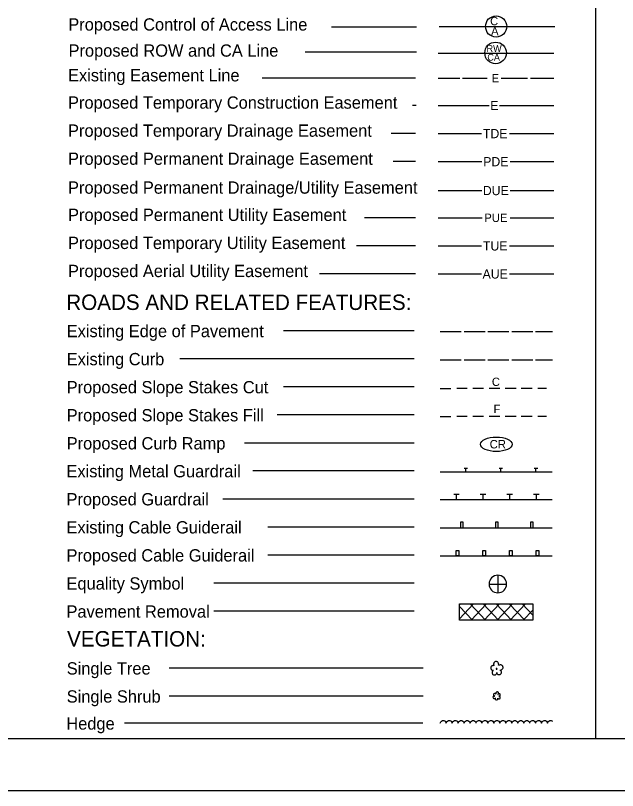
# Model space of a CAD drawing. Extents: x 2040834 to 2047174, y 618431 to 621625.
# Drawn here: x 2045579 to 2046085, y 620341 to 620991 of the extents above; entities that cross this region are included whole.
import ezdxf

# ---------------------------------------------------------------- set-up
doc = ezdxf.new("R2010")
doc.units = 0
doc.layers.add('Default', color=7, linetype='Continuous')

msp = doc.modelspace()

# ---------------------------------------------------------------- linework, layer by layer
at = {"layer": 'Default'}
for p, q in [((2046066.04, 621580.79), (2046066.01, 620384.96)), ((2045916.06, 620981.49), (2045844.59, 620981.49)), ((2045934.93, 620981.94), (2046032.04, 620981.94)), ((2045915.94, 620960.59), (2045822.52, 620960.59)), ((2045934.07, 620959.68), (2046031.18, 620959.68)), ((2045915.19, 620938.67), (2045786.59, 620938.67)), ((2045934.06, 620938.67), (2045952.32, 620938.67)), ((2045954.68, 620938.67), (2045975.27, 620938.67)), ((2045987.05, 620938.67), (2046009.12, 620938.67)), ((2046011.47, 620938.67), (2046031.17, 620938.67)), ((2045915.64, 620915.78), (2045912.68, 620915.78)), ((2045934.06, 620915.78), (2045937.14, 620915.78)), ((2045937.14, 620915.78), (2045976.86, 620915.78)), ((2045985.69, 620915.78), (2046025.42, 620915.78)), ((2046025.42, 620915.78), (2046031.17, 620915.78)), ((2045915.19, 620892.23), (2045894.6, 620892.23)), ((2045934.06, 620892.23), (2045938, 620892.23)), ((2045938, 620892.23), (2045970.37, 620892.23)), ((2045993.92, 620892.23), (2046026.29, 620892.23)), ((2046026.29, 620892.23), (2046031.17, 620892.23)), ((2045915.19, 620868.69), (2045896.35, 620868.69)), ((2045934.06, 620868.69), (2045938.53, 620868.69)), ((2045938.53, 620868.69), (2045970.9, 620868.69)), ((2045994.45, 620868.69), (2046026.82, 620868.69)), ((2046026.82, 620868.69), (2046031.17, 620868.69)), ((2045934.06, 620844.47), (2045970.9, 620844.47)), ((2045994.45, 620844.47), (2046031.17, 620844.47)), ((2045915.19, 620821.6), (2045872.33, 620821.6)), ((2045934.06, 620821.6), (2045938.58, 620821.6)), ((2045938.58, 620821.6), (2045970.95, 620821.6)), ((2045994.49, 620821.6), (2046026.86, 620821.6)), ((2046026.86, 620821.6), (2046031.17, 620821.6)), ((2045915.19, 620798.06), (2045865.59, 620798.06)), ((2045934.06, 620798.06), (2045938, 620798.06)), ((2045938, 620798.06), (2045970.37, 620798.06)), ((2045993.92, 620798.06), (2046026.29, 620798.06)), ((2046026.29, 620798.06), (2046031.17, 620798.06)), ((2045915.19, 620774.51), (2045834.61, 620774.51)), ((2045934.06, 620774.51), (2045938, 620774.51)), ((2045938, 620774.51), (2045970.37, 620774.51)), ((2045993.92, 620774.51), (2046026.29, 620774.51)), ((2046026.29, 620774.51), (2046031.17, 620774.51)), ((2045914.06, 620726.81), (2045804.31, 620726.81)), ((2045935.87, 620726.13), (2045953.53, 620726.13)), ((2045955.88, 620726.13), (2045973.54, 620726.13)), ((2045975.89, 620726.13), (2045993.55, 620726.13)), ((2045995.9, 620726.13), (2046013.56, 620726.13)), ((2046015.91, 620726.13), (2046030.04, 620726.13)), ((2045914.06, 620703.27), (2045717.31, 620703.27)), ((2045935.87, 620702.59), (2045953.53, 620702.59)), ((2045955.88, 620702.59), (2045973.54, 620702.59)), ((2045975.89, 620702.59), (2045993.55, 620702.59)), ((2045995.9, 620702.59), (2046013.56, 620702.59)), ((2046015.91, 620702.59), (2046030.04, 620702.59)), ((2045914.06, 620679.73), (2045804.37, 620679.73)), ((2045935.87, 620678.49), (2045944.82, 620678.49)), ((2045958.59, 620678.49), (2045949.7, 620678.49)), ((2045972.13, 620678.49), (2045963.18, 620678.49)), ((2045985.96, 620678.49), (2045976.78, 620678.49)), ((2045999.44, 620678.49), (2045990.31, 620678.49)), ((2046013.03, 620678.49), (2046003.79, 620678.49)), ((2046025.15, 620678.49), (2046017.62, 620678.49)), ((2045914.06, 620656.18), (2045799.01, 620656.18)), ((2045935.87, 620654.95), (2045944.82, 620654.95)), ((2045958.59, 620654.95), (2045949.7, 620654.95)), ((2045972.13, 620654.95), (2045963.18, 620654.95)), ((2045985.96, 620654.95), (2045976.78, 620654.95)), ((2045999.44, 620654.95), (2045990.31, 620654.95)), ((2046013.03, 620654.95), (2046003.79, 620654.95)), ((2046025.15, 620654.95), (2046017.62, 620654.95)), ((2045914.06, 620632.64), (2045771.72, 620632.64)), ((2045955.86, 620611.51), (2045958.8, 620611.51)), ((2045957.33, 620608.57), (2045957.33, 620611.51)), ((2045985.29, 620611.51), (2045988.23, 620611.51)), ((2045986.76, 620608.57), (2045986.76, 620611.51)), ((2046014.71, 620611.51), (2046017.66, 620611.51)), ((2046016.19, 620608.57), (2046016.19, 620611.51)), ((2045913.88, 620609.24), (2045778.7, 620609.24)), ((2045935.69, 620608.57), (2046029.86, 620608.57)), ((2045913.88, 620585.7), (2045753.51, 620585.7)), ((2046029.86, 620585.02), (2045935.69, 620585.02)), ((2045947.14, 620589.67), (2045951.84, 620589.67)), ((2045949.49, 620585.02), (2045949.49, 620589.67)), ((2045969.5, 620589.67), (2045974.21, 620589.67)), ((2045971.85, 620585.02), (2045971.85, 620589.67)), ((2045991.86, 620589.67), (2045996.57, 620589.67)), ((2045994.22, 620585.02), (2045994.22, 620589.67)), ((2046014.23, 620589.67), (2046018.94, 620589.67)), ((2046016.58, 620585.02), (2046016.58, 620589.67)), ((2045913.88, 620562.16), (2045791.11, 620562.16)), ((2045935.69, 620561.48), (2046029.86, 620561.48)), ((2045913.88, 620538.62), (2045791.11, 620538.62)), ((2045935.69, 620537.94), (2046029.86, 620537.94)), ((2045984.21, 620521.74), (2045984.21, 620514.38)), ((2045913.88, 620515.07), (2045745.99, 620515.07)), ((2045976.86, 620514.38), (2045984.21, 620514.38)), ((2045984.21, 620514.38), (2045984.21, 620507.03)), ((2045984.21, 620514.38), (2045991.57, 620514.38)), ((2045952.11, 620497.76), (2046013.43, 620497.76)), ((2045952.11, 620483.98), (2045952.11, 620497.76)), ((2045952.11, 620497.05), (2045952.76, 620497.76)), ((2045952.11, 620485.34), (2045963.7, 620497.76)), ((2045963, 620483.98), (2045952.11, 620495.64)), ((2045973.94, 620483.98), (2045961, 620497.76)), ((2045961.7, 620483.98), (2045974.65, 620497.76)), ((2045984.83, 620483.98), (2045971.94, 620497.76)), ((2045972.59, 620483.98), (2045985.6, 620497.76)), ((2045995.78, 620483.98), (2045982.83, 620497.76)), ((2045983.54, 620483.98), (2045996.48, 620497.76)), ((2046006.73, 620483.98), (2045993.72, 620497.76)), ((2045994.48, 620483.98), (2046007.37, 620497.76)), ((2046013.43, 620488.4), (2046004.67, 620497.76)), ((2046013.43, 620497.76), (2046013.43, 620483.98)), ((2045913.88, 620491.53), (2045745.99, 620491.53)), ((2046005.37, 620483.98), (2046013.43, 620492.58)), ((2046013.43, 620483.98), (2045952.11, 620483.98)), ((2045921.62, 620443.81), (2045708.42, 620443.81)), ((2045921.62, 620420.27), (2045708.42, 620420.27)), ((2045921.31, 620397.6), (2045670.95, 620397.6)), ((2045935.89, 620397.6), (2045936.25, 620398.72)), ((2045936.25, 620398.72), (2045936.95, 620399.48)), ((2045936.95, 620399.48), (2045937.89, 620400.01)), ((2045937.89, 620400.01), (2045939.01, 620400.01)), ((2045939.01, 620400.01), (2045939.95, 620399.42)), ((2045939.95, 620399.42), (2045940.6, 620398.66)), ((2045940.6, 620398.66), (2045940.84, 620397.66)), ((2045940.9, 620397.6), (2045941.25, 620398.72)), ((2045941.25, 620398.72), (2045941.96, 620399.48)), ((2045941.96, 620399.48), (2045942.9, 620400.01)), ((2045942.9, 620400.01), (2045944.02, 620400.01)), ((2045944.02, 620400.01), (2045944.96, 620399.42)), ((2045944.96, 620399.42), (2045945.6, 620398.66)), ((2045945.6, 620398.66), (2045945.84, 620397.66)), ((2045945.9, 620397.6), (2045946.25, 620398.72)), ((2045946.25, 620398.72), (2045946.96, 620399.48)), ((2045946.96, 620399.48), (2045947.9, 620400.01)), ((2045947.9, 620400.01), (2045949.02, 620400.01)), ((2045949.02, 620400.01), (2045949.96, 620399.42)), ((2045949.96, 620399.42), (2045950.61, 620398.66)), ((2045950.61, 620398.66), (2045950.84, 620397.66)), ((2045950.9, 620397.6), (2045951.25, 620398.72)), ((2045951.25, 620398.72), (2045951.96, 620399.48)), ((2045951.96, 620399.48), (2045952.9, 620400.01)), ((2045952.9, 620400.01), (2045954.02, 620400.01)), ((2045954.02, 620400.01), (2045954.96, 620399.42)), ((2045954.96, 620399.42), (2045955.61, 620398.66)), ((2045955.61, 620398.66), (2045955.85, 620397.66)), ((2045955.9, 620397.6), (2045956.26, 620398.72)), ((2045956.26, 620398.72), (2045956.96, 620399.48)), ((2045956.96, 620399.48), (2045957.91, 620400.01)), ((2045957.91, 620400.01), (2045959.02, 620400.01)), ((2045959.02, 620400.01), (2045959.97, 620399.42)), ((2045959.97, 620399.42), (2045960.61, 620398.66)), ((2045960.61, 620398.66), (2045960.85, 620397.66)), ((2045960.91, 620397.6), (2045961.26, 620398.72)), ((2045961.26, 620398.72), (2045961.97, 620399.48)), ((2045961.97, 620399.48), (2045962.91, 620400.01)), ((2045962.91, 620400.01), (2045964.03, 620400.01)), ((2045964.03, 620400.01), (2045964.97, 620399.42)), ((2045964.97, 620399.42), (2045965.62, 620398.66)), ((2045965.62, 620398.66), (2045965.85, 620397.66)), ((2045965.91, 620397.6), (2045966.26, 620398.72)), ((2045966.26, 620398.72), (2045966.97, 620399.48)), ((2045966.97, 620399.48), (2045967.91, 620400.01)), ((2045967.91, 620400.01), (2045969.03, 620400.01)), ((2045969.03, 620400.01), (2045969.97, 620399.42)), ((2045969.97, 620399.42), (2045970.62, 620398.66)), ((2045970.62, 620398.66), (2045970.85, 620397.66)), ((2045970.91, 620397.6), (2045971.27, 620398.72)), ((2045971.27, 620398.72), (2045971.97, 620399.48)), ((2045971.97, 620399.48), (2045972.91, 620400.01)), ((2045972.91, 620400.01), (2045974.03, 620400.01)), ((2045974.03, 620400.01), (2045974.97, 620399.42)), ((2045974.97, 620399.42), (2045975.62, 620398.66)), ((2045975.62, 620398.66), (2045975.86, 620397.66)), ((2045975.91, 620397.6), (2045976.27, 620398.72)), ((2045976.27, 620398.72), (2045976.97, 620399.48)), ((2045976.97, 620399.48), (2045977.92, 620400.01)), ((2045977.92, 620400.01), (2045979.03, 620400.01)), ((2045979.03, 620400.01), (2045979.98, 620399.42)), ((2045979.98, 620399.42), (2045980.62, 620398.66)), ((2045980.62, 620398.66), (2045980.86, 620397.66)), ((2045980.92, 620397.6), (2045981.27, 620398.72)), ((2045981.27, 620398.72), (2045981.98, 620399.48)), ((2045981.98, 620399.48), (2045982.92, 620400.01)), ((2045982.92, 620400.01), (2045984.04, 620400.01)), ((2045984.04, 620400.01), (2045984.98, 620399.42)), ((2045984.98, 620399.42), (2045985.63, 620398.66)), ((2045985.63, 620398.66), (2045985.86, 620397.66)), ((2045985.92, 620397.6), (2045986.27, 620398.72)), ((2045986.27, 620398.72), (2045986.98, 620399.48)), ((2045986.98, 620399.48), (2045987.92, 620400.01)), ((2045987.92, 620400.01), (2045989.04, 620400.01)), ((2045989.04, 620400.01), (2045989.98, 620399.42)), ((2045989.98, 620399.42), (2045990.63, 620398.66)), ((2045990.63, 620398.66), (2045990.86, 620397.66)), ((2045990.92, 620397.6), (2045991.28, 620398.72)), ((2045991.28, 620398.72), (2045991.98, 620399.48)), ((2045991.98, 620399.48), (2045992.92, 620400.01)), ((2045992.92, 620400.01), (2045994.04, 620400.01)), ((2045994.04, 620400.01), (2045994.98, 620399.42)), ((2045994.98, 620399.42), (2045995.63, 620398.66)), ((2045995.63, 620398.66), (2045995.87, 620397.66)), ((2045995.93, 620397.6), (2045996.28, 620398.72)), ((2045996.28, 620398.72), (2045996.98, 620399.48)), ((2045996.98, 620399.48), (2045997.93, 620400.01)), ((2045997.93, 620400.01), (2045999.04, 620400.01)), ((2045999.04, 620400.01), (2045999.99, 620399.42)), ((2045999.99, 620399.42), (2046000.63, 620398.66)), ((2046000.63, 620398.66), (2046000.87, 620397.66)), ((2046000.93, 620397.6), (2046001.28, 620398.72)), ((2046001.28, 620398.72), (2046001.99, 620399.48)), ((2046001.99, 620399.48), (2046002.93, 620400.01)), ((2046002.93, 620400.01), (2046004.05, 620400.01)), ((2046004.05, 620400.01), (2046004.99, 620399.42)), ((2046004.99, 620399.42), (2046005.64, 620398.66)), ((2046005.64, 620398.66), (2046005.87, 620397.66)), ((2046005.93, 620397.6), (2046006.28, 620398.72)), ((2046006.28, 620398.72), (2046006.99, 620399.48)), ((2046006.99, 620399.48), (2046007.93, 620400.01)), ((2046007.93, 620400.01), (2046009.05, 620400.01)), ((2046009.05, 620400.01), (2046009.99, 620399.42)), ((2046009.99, 620399.42), (2046010.64, 620398.66)), ((2046010.64, 620398.66), (2046010.87, 620397.66)), ((2046010.93, 620397.6), (2046011.29, 620398.72)), ((2046011.29, 620398.72), (2046011.99, 620399.48)), ((2046011.99, 620399.48), (2046012.93, 620400.01)), ((2046012.93, 620400.01), (2046014.05, 620400.01)), ((2046014.05, 620400.01), (2046014.99, 620399.42)), ((2046014.99, 620399.42), (2046015.64, 620398.66)), ((2046015.64, 620398.66), (2046015.88, 620397.66)), ((2046015.94, 620397.6), (2046016.29, 620398.72)), ((2046016.29, 620398.72), (2046017, 620399.48)), ((2046017, 620399.48), (2046017.94, 620400.01)), ((2046017.94, 620400.01), (2046019.06, 620400.01)), ((2046019.06, 620400.01), (2046020, 620399.42)), ((2046020, 620399.42), (2046020.64, 620398.66)), ((2046020.64, 620398.66), (2046020.88, 620397.66)), ((2046020.94, 620397.6), (2046021.29, 620398.72)), ((2046021.29, 620398.72), (2046022, 620399.48)), ((2046022, 620399.48), (2046022.94, 620400.01)), ((2046022.94, 620400.01), (2046024.06, 620400.01)), ((2046024.06, 620400.01), (2046025, 620399.42)), ((2046025, 620399.42), (2046025.65, 620398.66)), ((2046025.65, 620398.66), (2046025.88, 620397.66)), ((2046025.94, 620397.6), (2046026.29, 620398.72)), ((2046026.29, 620398.72), (2046027, 620399.48)), ((2046027, 620399.48), (2046027.94, 620400.01)), ((2046027.94, 620400.01), (2046029.06, 620400.01)), ((2046029.06, 620400.01), (2046030, 620399.42)), ((2046030, 620399.42), (2046030.06, 620399.36)), ((2045118.13, 620384.96), (2047013.93, 620384.96)), ((2045074.38, 620341.21), (2047057.71, 620341.21))]:
    msp.add_line(p, q, dxfattribs=at)
for points in [[(2045952.73, 620561.48), (2045955.08, 620561.48), (2045955.08, 620566.19), (2045952.73, 620566.19)], [(2045982.15, 620561.48), (2045984.51, 620561.48), (2045984.51, 620566.19), (2045982.15, 620566.19)], [(2046011.58, 620561.48), (2046013.94, 620561.48), (2046013.94, 620566.19), (2046011.58, 620566.19)], [(2045949.18, 620542.65), (2045951.53, 620542.65), (2045951.53, 620537.94), (2045949.18, 620537.94)], [(2045971.55, 620542.65), (2045973.9, 620542.65), (2045973.9, 620537.94), (2045971.55, 620537.94)], [(2045993.91, 620542.65), (2045996.26, 620542.65), (2045996.26, 620537.94), (2045993.91, 620537.94)], [(2046016.27, 620542.65), (2046018.63, 620542.65), (2046018.63, 620537.94), (2046016.27, 620537.94)]]:
    msp.add_lwpolyline(points, close=True, dxfattribs=at)
for points in [[(2045984.64, 620446.27), (2045984.82, 620446.68), (2045984.91, 620447.1), (2045984.87, 620447.56), (2045984.78, 620447.98), (2045984.54, 620448.4), (2045984.31, 620448.72), (2045983.94, 620449.05), (2045983.57, 620449.23), (2045983.11, 620449.37), (2045982.69, 620449.37), (2045982.23, 620449.32), (2045981.81, 620449.18), (2045981.44, 620448.95), (2045981.11, 620448.63), (2045980.88, 620448.26), (2045980.7, 620447.84), (2045980.65, 620447.42), (2045980.65, 620446.96), (2045980.74, 620446.54), (2045980.93, 620446.13), (2045981.21, 620445.76), (2045980.84, 620445.94), (2045980.42, 620446.03), (2045980, 620445.99), (2045979.59, 620445.89), (2045979.21, 620445.71), (2045978.84, 620445.43), (2045978.61, 620445.11), (2045978.38, 620444.74), (2045978.29, 620444.36), (2045978.24, 620443.9), (2045978.29, 620443.48), (2045978.47, 620443.11), (2045978.7, 620442.74), (2045978.98, 620442.46), (2045979.35, 620442.23), (2045979.72, 620442.05), (2045980.14, 620442), (2045980.56, 620442), (2045980.19, 620441.82), (2045979.86, 620441.54), (2045979.63, 620441.21), (2045979.45, 620440.8), (2045979.35, 620440.38), (2045979.31, 620439.96), (2045979.4, 620439.55), (2045979.59, 620439.17), (2045979.82, 620438.8), (2045980.09, 620438.53), (2045980.46, 620438.29), (2045980.88, 620438.15), (2045981.3, 620438.11), (2045981.72, 620438.15), (2045982.13, 620438.25), (2045982.51, 620438.48), (2045982.83, 620438.76), (2045983.06, 620439.08), (2045983.25, 620439.45), (2045983.34, 620439.87)], [(2045983.34, 620443.67), (2045983.15, 620443.67), (2045982.97, 620443.62), (2045982.88, 620443.48), (2045982.83, 620443.3), (2045982.88, 620443.11), (2045983.02, 620442.97), (2045983.2, 620442.97), (2045983.39, 620443.02), (2045983.52, 620443.16), (2045983.57, 620443.34), (2045983.48, 620443.53), (2045983.34, 620443.67)], [(2045983.2, 620440.38), (2045983.25, 620439.92), (2045983.39, 620439.5), (2045983.62, 620439.13), (2045983.94, 620438.8), (2045984.31, 620438.57), (2045984.73, 620438.43), (2045985.19, 620438.39), (2045985.61, 620438.43), (2045986.03, 620438.57), (2045986.4, 620438.8), (2045986.72, 620439.08), (2045987, 620439.45), (2045987.14, 620439.87), (2045987.23, 620440.29), (2045987.19, 620440.75), (2045987.09, 620441.17), (2045986.86, 620441.58), (2045986.58, 620441.91), (2045986.21, 620442.14), (2045985.8, 620442.33), (2045986.26, 620442.28), (2045986.72, 620442.28), (2045987.14, 620442.42), (2045987.56, 620442.6), (2045987.93, 620442.88), (2045988.21, 620443.25), (2045988.44, 620443.67), (2045988.53, 620444.09), (2045988.58, 620444.55), (2045988.48, 620445.01), (2045988.34, 620445.43), (2045988.07, 620445.8), (2045987.74, 620446.13), (2045987.37, 620446.36), (2045986.91, 620446.54), (2045986.49, 620446.59), (2045986.03, 620446.59), (2045985.56, 620446.45), (2045985.19, 620446.22), (2045984.82, 620445.94)], [(2045982.64, 620421.98), (2045982.51, 620422.26), (2045982.23, 620422.49), (2045981.95, 620422.68), (2045981.62, 620422.72), (2045981.3, 620422.68), (2045980.98, 620422.58), (2045980.7, 620422.35), (2045980.51, 620422.07), (2045980.42, 620421.75), (2045980.42, 620421.42), (2045980.51, 620421.1), (2045980.7, 620420.82), (2045980.98, 620420.59), (2045981.3, 620420.45), (2045981.62, 620420.45), (2045981.3, 620420.5), (2045980.98, 620420.5), (2045980.7, 620420.41), (2045980.42, 620420.22), (2045980.24, 620419.99), (2045980.14, 620419.71), (2045980.09, 620419.39), (2045980.14, 620419.06), (2045980.28, 620418.78), (2045980.51, 620418.55), (2045980.79, 620418.41), (2045981.07, 620418.32), (2045981.39, 620418.37), (2045981.67, 620418.46), (2045981.95, 620418.64), (2045982.13, 620418.88), (2045982, 620418.55), (2045981.95, 620418.23), (2045982.04, 620417.9), (2045982.18, 620417.63), (2045982.41, 620417.35), (2045982.69, 620417.21), (2045983.02, 620417.12), (2045983.34, 620417.16), (2045983.66, 620417.26), (2045983.94, 620417.44), (2045984.13, 620417.72), (2045984.27, 620418.04), (2045984.27, 620418.37), (2045984.22, 620418.69), (2045984.36, 620418.46), (2045984.64, 620418.23), (2045984.91, 620418.13), (2045985.24, 620418.09), (2045985.56, 620418.13), (2045985.84, 620418.27), (2045986.07, 620418.51), (2045986.21, 620418.78), (2045986.26, 620419.11), (2045986.26, 620419.43), (2045986.12, 620419.71), (2045985.93, 620419.94), (2045985.7, 620420.13), (2045985.38, 620420.27), (2045985.05, 620420.27), (2045985.38, 620420.27), (2045985.7, 620420.36), (2045985.93, 620420.54), (2045986.17, 620420.82), (2045986.26, 620421.1), (2045986.26, 620421.42), (2045986.21, 620421.75), (2045986.03, 620422.03), (2045985.8, 620422.21), (2045985.47, 620422.35), (2045985.15, 620422.4), (2045984.87, 620422.31), (2045984.54, 620422.17), (2045984.36, 620421.93), (2045984.22, 620421.66)], [(2045984.08, 620421.66), (2045984.36, 620421.8), (2045984.59, 620422.07), (2045984.73, 620422.35), (2045984.78, 620422.68), (2045984.78, 620423), (2045984.64, 620423.32), (2045984.45, 620423.56), (2045984.22, 620423.79), (2045983.89, 620423.88), (2045983.57, 620423.93), (2045983.25, 620423.88), (2045982.97, 620423.74), (2045982.69, 620423.51), (2045982.55, 620423.23), (2045982.46, 620422.91), (2045982.46, 620422.58), (2045982.51, 620422.26), (2045982.69, 620421.98)]]:
    msp.add_lwpolyline(points, dxfattribs=at)
for centre, radius in [((2045982.77, 620982.06), 8.92), ((2045982.32, 620959.86), 9.08)]:
    msp.add_circle(centre, radius, dxfattribs=at)
for start, end in [(89.99439, 179.99893), (359.99439, 89.99893), (179.99439, 269.99892), (269.99439, 359.99893)]:
    msp.add_arc((2045984.21, 620514.38), 7.36, start, end, dxfattribs=at)
msp.add_ellipse((2045982.91, 620631.62), major_axis=(13.2, 0), ratio=0.462467, dxfattribs=at)

# ---------------------------------------------------------------- texts
for s, height, p in [('Proposed Control of Access Line', 10.2996, (2045623.79, 620978.63)), ('C', 6.99, (2045977.73, 620983.11)), ('A', 6.99, (2045978.56, 620974.71)), ('Proposed ROW and CA Line', 10.2996, (2045623.99, 620956.73)), ('RW', 5.695, (2045974.73, 620960.76)), ('CA', 5.695, (2045975.39, 620953.36)), ('Existing Easement Line', 10.2996, (2045623.57, 620936.01)), ('E', 7.06, (2045979.04, 620935.14)), ('Proposed Temporary Construction Easement', 10.2996, (2045623.57, 620913.11)), ('E', 7.71, (2045977.87, 620911.89)), ('Proposed Temporary Drainage Easement', 10.2996, (2045623.57, 620889.57)), ('TDE', 7.71, (2045971.68, 620888.35)), ('Proposed Permanent Drainage Easement', 10.2996, (2045623.57, 620866.03)), ('PDE', 7.71, (2045971.91, 620864.81)), ('Proposed Permanent Drainage/Utility Easement', 10.2996, (2045623.57, 620841.8)), ('DUE', 7.71, (2045971.61, 620840.58)), ('Proposed Permanent Utility Easement', 10.2996, (2045623.57, 620818.93)), ('PUE', 7.063, (2045972.84, 620818.07)), ('Proposed Temporary Utility Easement', 10.2996, (2045623.57, 620795.39)), ('TUE', 7.71, (2045971.68, 620794.17)), ('Proposed Aerial Utility Easement', 10.2996, (2045623.57, 620771.85)), ('AUE', 7.71, (2045971.38, 620770.63)), ('ROADS AND RELATED FEATURES:', 12.9481, (2045622.08, 620744.28)), ('Existing Edge of Pavement', 10.2996, (2045622.44, 620721.45)), ('Existing Curb', 10.2996, (2045622.44, 620697.91)), ('Proposed Slope Stakes Cut', 10.2996, (2045622.44, 620674.37)), ('C', 6.98, (2045979.19, 620680.54)), ('F', 6.98, (2045980.6, 620657.73)), ('Proposed Slope Stakes Fill', 10.2996, (2045622.44, 620650.83)), ('Proposed Curb Ramp', 10.2996, (2045622.44, 620627.29)), ('CR', 7.063, (2045977.37, 620628.15)), ('Existing Metal Guardrail', 10.2996, (2045622.25, 620603.89)), ('Proposed Guardrail', 10.2996, (2045622.27, 620580.36)), ('Existing Cable Guiderail', 10.2996, (2045622.27, 620556.82)), ('Proposed Cable Guiderail', 10.2996, (2045622.27, 620533.28)), ('Equality Symbol', 10.2996, (2045622.27, 620509.73)), ('Pavement Removal', 10.2996, (2045622.27, 620486.19)), ('VEGETATION:', 12.9481, (2045622.77, 620461.99)), ('Single Tree', 10.2996, (2045622.45, 620438.48)), ('Single Shrub', 10.2996, (2045622.45, 620414.94)), ('Hedge', 10.3, (2045622.13, 620392.27))]:
    msp.add_text(s, height=height, dxfattribs=at).set_placement(p)

doc.saveas('drawing.dxf')
